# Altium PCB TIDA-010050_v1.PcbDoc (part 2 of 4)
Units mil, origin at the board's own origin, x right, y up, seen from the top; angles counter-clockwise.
Board outline 2060.77 x 1300 mil, 4 copper layers (Top Layer, signal1, signal2, Bottom Layer), stack 23.6 mil thick; 58 components, 30 nets, 158 pads, 41 vias.
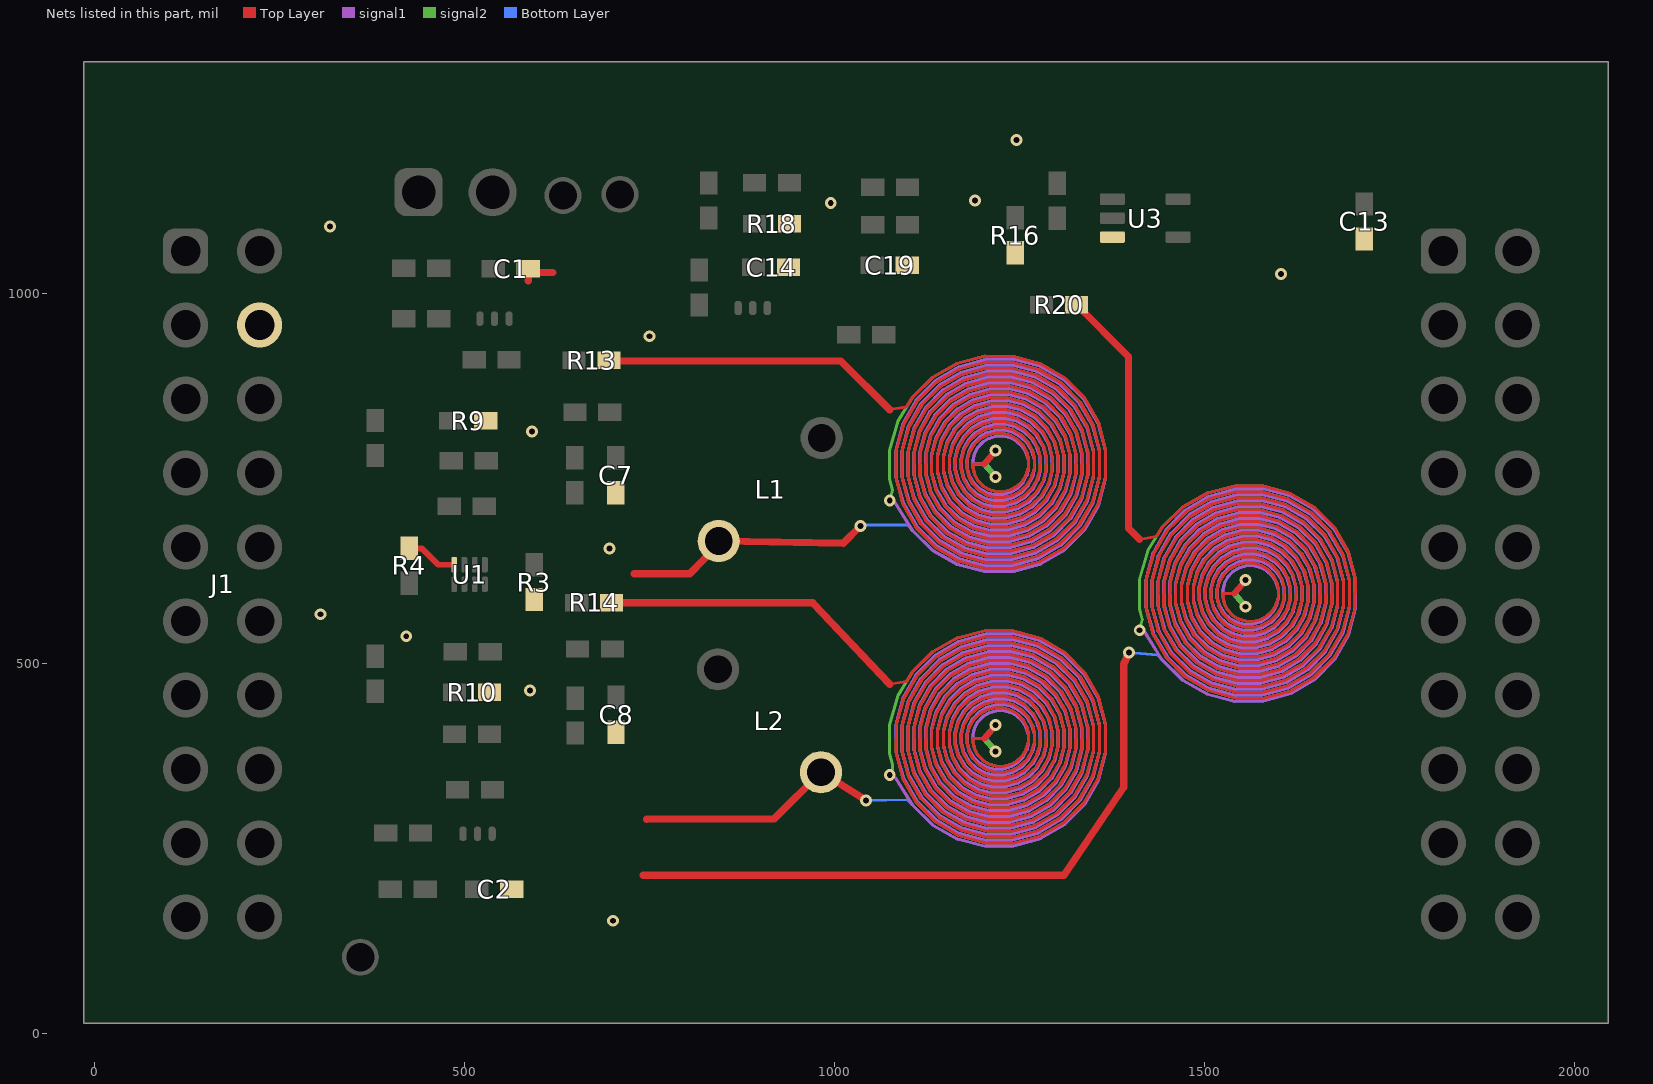
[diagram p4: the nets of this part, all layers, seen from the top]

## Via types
v1: diameter 16, hole 8, Top Layer to Bottom Layer, 40 vias
v2: diameter 16/16/16/16 (per signal layer), hole 8, Top Layer to Bottom Layer, 1 vias

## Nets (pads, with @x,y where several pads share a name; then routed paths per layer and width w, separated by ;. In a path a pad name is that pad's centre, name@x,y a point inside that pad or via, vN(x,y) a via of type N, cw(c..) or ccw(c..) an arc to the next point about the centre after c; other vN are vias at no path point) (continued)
GND: C1.2 C2.2 C7.2 C8.2 C13.2 C14.2 C19.2 J1.4 L1.1 L2.1 R3.1 R4.1 R9.1 R10.1 R13.1 R14.1 R16.1 R18.1 R20.1 U1.4 U3.3 | length 100215
  Top Layer w4: 1074.32,471.5 1096.71,475.12 1105.24,488.24 1132.74,515.27 1166.23,534.22 1203.4,543.83 1241.69,543.5 1278.52,533.29 1311.37,513.94 1338.03,486.8 1356.71,453.77 1366.19,417.12 1365.86,379.34 1355.78,343.03 1336.69,310.64 1309.93,284.35 1277.36,265.93 1241.21,256.59 1203.97,256.92 1168.16,266.86 1136.22,285.68 1110.31,312.07 1092.15,344.19 1082.94,379.83 1083.28,416.55 1093.08,451.84 1111.64,483.32 1137.66,508.87 1169.32,526.76 1204.45,535.83 1240.64,535.5 1275.43,525.83 1306.46,507.53 1331.63,481.89 1349.26,450.69 1358.19,416.06 1357.86,380.4 1348.33,346.12 1330.29,315.55 1305.02,290.75 1274.27,273.38 1240.16,264.59 1205.02,264.92 1171.25,274.31 1141.13,292.08 1116.71,316.98 1099.6,347.28 1090.94,380.88 1091.28,415.49 1100.54,448.76 1118.04,478.41 1142.57,502.47 1172.41,519.31 1205.5,527.83 1239.59,527.5 1272.34,518.38 1301.54,501.13 1325.22,476.98 1341.8,447.6 1350.19,415.01 1349.86,381.45 1340.87,349.2 1323.89,320.46 1300.11,297.15 1271.18,280.84 1239.11,272.59 1206.07,272.92 1174.34,281.77 1146.05,298.49 1123.11,321.89 1107.06,350.36 1098.94,381.93 1099.28,414.44 1107.99,445.67 1124.44,473.5 1147.48,496.06 1175.49,511.85 1206.56,519.83 1238.54,519.5 1269.25,510.92 1296.63,494.73 1318.82,472.07 1334.35,444.51 1342.19,413.96 1341.86,382.5 1333.42,352.29 1317.49,325.37 1295.2,303.55 1268.1,288.29 1238.05,280.59 1207.13,280.92 1177.42,289.22 1150.96,304.89 1129.51,326.8 1114.51,353.45 1106.94,382.99 1107.28,413.39 1115.44,442.58 1130.85,468.59 1152.39,489.66 1178.58,504.4 1207.61,511.83 1237.48,511.5 1266.17,503.47 1291.72,488.33 1312.42,467.16 1326.89,441.42 1334.19,412.9 1333.86,383.56 1325.96,355.38 1311.09,330.28 1290.29,309.95 1265.01,295.75 1237,288.59 1208.18,288.92 1180.51,296.68 1155.87,311.29 1135.91,331.72 1121.97,356.54 1114.94,384.04 1115.28,412.33 1122.9,439.49 1137.25,463.68 1157.3,483.26 1181.67,496.94 1208.66,503.83 1236.43,503.5 1263.08,496.01 1286.81,481.93 1306.02,462.24 1319.44,438.33 1326.19,411.85 1325.86,384.61 1318.51,358.47 1304.69,335.2 1285.37,316.36 1261.92,303.2 1235.95,296.59 1209.23,296.92 1183.6,304.13 1160.78,317.69 1142.32,336.63 1129.42,359.63 1122.94,385.09 1123.28,411.28 1130.35,436.4 1143.65,458.76 1162.22,476.86 1184.76,489.49 1209.71,495.83 1235.38,495.5 1259.99,488.56 1281.89,475.53 1299.62,457.33 1311.98,435.25 1318.19,410.8 1317.86,385.66 1311.05,361.56 1298.28,340.11 1280.46,322.76 1258.83,310.65 1234.89,304.59 1210.29,304.92 1186.69,311.59 1165.7,324.09 1148.72,341.54 1136.88,362.71 1130.94,386.15 1131.28,410.23 1137.81,433.32 1150.05,453.85 1167.13,470.46 1187.85,482.03 1210.77,487.83 1234.32,487.5 1256.9,481.1 1276.98,469.12 1293.22,452.42 1304.53,432.16 1310.19,409.74 1309.86,386.72 1303.6,364.64 1291.88,345.02 1275.55,329.16 1255.74,318.11 1233.84,312.59 1211.34,312.92 1189.78,319.04 1170.61,330.49 1155.12,346.45 1144.33,365.8 1138.94,387.2 1139.28,409.17 1145.26,430.23 1156.45,448.94 1172.04,464.06 1190.93,474.58 1211.82,479.83 1233.27,479.5 1253.81,473.65 1272.07,462.72 1286.81,447.51 1297.07,429.07 1302.19,408.69 1301.86,387.77 1296.14,367.73 1285.48,349.93 1270.64,335.56 1252.66,325.56 1232.79,320.59 1212.39,320.92 1192.86,326.5 1175.52,336.89 1161.52,351.37 1151.79,368.89 1146.94,388.25 1147.28,408.12 1152.72,427.14 1162.85,444.03 1176.95,457.65 1194.02,467.12 1212.87,471.83 1232.22,471.5 1250.73,466.19 1267.16,456.32 1280.41,442.59 1289.62,425.98 1294.19,407.64 1293.86,388.82 1288.69,370.82 1279.08,354.84 1265.73,341.96 1249.57,333.02 1231.73,328.59 1213.44,328.92 1195.95,333.95 1180.43,343.3 1167.92,356.28 1159.24,371.98 1154.94,389.31 1155.28,407.07 1160.17,424.05 1169.26,439.12 1181.86,451.25 1197.11,459.67 1213.93,463.83 1231.16,463.5 1247.64,458.74 1262.25,449.92 1274.01,437.68 1282.16,422.89 1286.19,406.58 1285.86,389.88 1281.23,373.91 1272.68,359.76 1260.81,348.36 1246.48,340.47 1230.68,336.59 1214.5,336.92 1199.04,341.41 1185.34,349.7 1174.32,361.19 1166.7,375.07 1162.94,390.36 1163.28,406.01 1167.63,420.96 1175.66,434.2 1186.78,444.85 1200.2,452.21 1214.98,455.83 1230.11,455.5 1244.55,451.28 1257.33,443.52 1267.61,432.77 1274.71,419.81 1278.19,405.53 1277.86,390.93 1273.78,377 1266.28,364.67 1255.9,354.77 1243.39,347.93 1229.63,344.59 1215.55,344.92 1202.13,348.86 1190.26,356.1 1180.72,366.1 1174.15,378.15 1170.94,391.41 1171.28,404.96 1175.08,417.88 1182.06,429.29 1191.69,438.45 1203.28,444.76 1216.03,447.83 1229.06,447.5 1241.46,443.83 1252.42,437.12 1261.21,427.86 1267.25,416.72 1270.19,404.48 1269.86,391.98 1266.32,380.08 1259.87,369.58 1250.99,361.17 1240.31,355.38 1228.57,352.59 1216.6,352.92 1205.21,356.32 1195.17,362.5 1187.13,371.01 1181.61,381.24 1178.94,392.47 1179.28,403.91 1182.54,414.79 1188.46,424.38 1196.6,432.05 1206.37,437.3 1217.09,439.83 1228,439.5 1238.38,436.37 1247.51,430.71 1254.81,422.95 1259.8,413.63 1262.19,403.42 1261.86,393.04 1258.87,383.17 1253.47,374.49 1246.08,367.57 1237.22,362.84 1227.52,360.59 1217.66,360.92 1208.3,363.77 1200.08,368.9 1193.53,375.93 1189.06,384.33 1186.94,393.52 1187.28,398.21 1202.53,398.21 ; 1074.31,842.61 1096.71,846.24 1105.24,859.35 1132.74,886.38 1166.23,905.33 1203.39,914.94 1241.69,914.61 1278.51,904.4 1311.36,885.05 1338.02,857.92 1356.71,824.89 1366.19,788.23 1365.85,750.46 1355.78,714.14 1336.69,681.75 1309.93,655.46 1277.36,637.04 1241.21,627.7 1203.96,628.03 1168.16,637.97 1136.22,656.79 1110.3,683.18 1092.15,715.3 1082.94,750.94 1083.27,787.66 1093.08,822.96 1111.64,854.44 1137.65,879.98 1169.31,897.88 1204.45,906.94 1240.64,906.61 1275.43,896.94 1306.45,878.65 1331.62,853 1349.25,821.8 1358.19,787.18 1357.85,751.51 1348.32,717.23 1330.29,686.66 1305.02,661.86 1274.27,644.49 1240.16,635.7 1205.02,636.03 1171.24,645.43 1141.13,663.2 1116.71,688.09 1099.6,718.39 1090.94,751.99 1091.27,786.61 1100.53,819.87 1118.04,849.52 1142.56,873.58 1172.4,890.42 1205.5,898.94 1239.58,898.61 1272.34,889.49 1301.54,872.24 1325.22,848.09 1341.8,818.71 1350.19,786.12 1349.85,752.56 1340.87,720.32 1323.89,691.57 1300.11,668.26 1271.18,651.95 1239.1,643.7 1206.07,644.03 1174.33,652.88 1146.04,669.6 1123.11,693.01 1107.05,721.48 1098.94,753.05 1099.27,785.55 1107.99,816.78 1124.44,844.61 1147.48,867.18 1175.49,882.97 1206.55,890.94 1238.53,890.61 1269.25,882.03 1296.63,865.84 1318.82,843.18 1334.34,815.62 1342.19,785.07 1341.85,753.62 1333.41,723.41 1317.49,696.48 1295.19,674.67 1268.09,659.4 1238.05,651.7 1207.12,652.03 1177.42,660.33 1150.96,676 1129.51,697.92 1114.51,724.56 1106.94,754.1 1107.27,784.5 1115.44,813.69 1130.84,839.7 1152.39,860.77 1178.58,875.51 1207.6,882.94 1237.48,882.61 1266.16,874.58 1291.72,859.44 1312.42,838.27 1326.89,812.53 1334.19,784.02 1333.85,754.67 1325.96,726.49 1311.08,701.4 1290.28,681.07 1265.01,666.86 1237,659.7 1208.18,660.03 1180.51,667.79 1155.87,682.4 1135.91,702.83 1121.96,727.65 1114.94,755.15 1115.27,783.45 1122.9,810.6 1137.24,834.79 1157.3,854.37 1181.67,868.06 1208.66,874.94 1236.43,874.61 1263.08,867.12 1286.8,853.04 1306.02,833.36 1319.44,809.45 1326.19,782.96 1325.85,755.72 1318.5,729.58 1304.68,706.31 1285.37,687.47 1261.92,674.31 1235.94,667.7 1209.23,668.03 1183.6,675.24 1160.78,688.8 1142.31,707.74 1129.42,730.74 1122.94,756.2 1123.27,782.39 1130.35,807.52 1143.65,829.88 1162.21,847.97 1184.75,860.6 1209.71,866.94 1235.37,866.61 1259.99,859.67 1281.89,846.64 1299.61,828.44 1311.98,806.36 1318.19,781.91 1317.85,756.78 1311.05,732.67 1298.28,711.22 1280.46,693.87 1258.83,681.77 1234.89,675.7 1210.28,676.03 1186.68,682.7 1165.69,695.2 1148.71,712.65 1136.87,733.83 1130.94,757.26 1131.27,781.34 1137.81,804.43 1150.05,824.96 1167.12,841.57 1187.84,853.15 1210.76,858.94 1234.32,858.61 1256.9,852.21 1276.98,840.24 1293.21,823.53 1304.53,803.27 1310.19,780.86 1309.85,757.83 1303.59,735.76 1291.88,716.13 1275.55,700.27 1255.74,689.22 1233.84,683.7 1211.34,684.03 1189.77,690.15 1170.6,701.61 1155.12,717.57 1144.33,736.91 1138.94,758.31 1139.27,780.29 1145.26,801.34 1156.45,820.05 1172.04,835.17 1190.93,845.69 1211.82,850.94 1233.27,850.61 1253.81,844.76 1272.07,833.83 1286.81,818.62 1297.07,800.18 1302.19,779.8 1301.85,758.88 1296.14,738.84 1285.48,721.05 1270.63,706.67 1252.65,696.68 1232.78,691.7 1212.39,692.03 1192.86,697.61 1175.52,708.01 1161.52,722.48 1151.78,740 1146.94,759.36 1147.27,779.23 1152.72,798.25 1162.85,815.14 1176.95,828.77 1194.02,838.24 1212.87,842.94 1232.21,842.61 1250.72,837.3 1267.15,827.43 1280.41,813.71 1289.62,797.09 1294.19,778.75 1293.85,759.94 1288.68,741.93 1279.08,725.96 1265.72,713.08 1249.57,704.13 1231.73,699.7 1213.44,700.03 1195.95,705.06 1180.43,714.41 1167.92,727.39 1159.24,743.09 1154.94,760.42 1155.27,778.18 1160.17,795.16 1169.25,810.23 1181.86,822.37 1197.11,830.78 1213.92,834.94 1231.16,834.61 1247.64,829.85 1262.24,821.03 1274.01,808.8 1282.16,794.01 1286.19,777.7 1285.85,760.99 1281.23,745.02 1272.67,730.87 1260.81,719.48 1246.48,711.59 1230.68,707.7 1214.49,708.03 1199.04,712.52 1185.34,720.81 1174.32,732.3 1166.69,746.18 1162.94,761.47 1163.27,777.13 1167.63,792.08 1175.65,805.32 1186.77,815.96 1200.19,823.33 1214.98,826.94 1230.11,826.61 1244.55,822.4 1257.33,814.63 1267.61,803.88 1274.71,790.92 1278.19,776.64 1277.85,762.04 1273.77,748.11 1266.27,735.78 1255.9,725.88 1243.39,719.04 1229.62,715.7 1215.55,716.03 1202.12,719.97 1190.25,727.21 1180.72,737.21 1174.15,749.27 1170.94,762.52 1171.27,776.07 1175.08,788.99 1182.06,800.4 1191.69,809.56 1203.28,815.87 1216.03,818.94 1229.05,818.61 1241.46,814.94 1252.42,808.23 1261.2,798.97 1267.25,787.83 1270.19,775.59 1269.85,763.09 1266.32,751.2 1259.87,740.69 1250.99,732.28 1240.3,726.5 1228.57,723.7 1216.6,724.03 1205.21,727.43 1195.16,733.61 1187.12,742.13 1181.6,752.35 1178.94,763.58 1179.27,775.02 1182.53,785.9 1188.46,795.49 1196.6,803.16 1206.37,808.42 1217.08,810.94 1228,810.61 1238.37,807.49 1247.51,801.83 1254.8,794.06 1259.8,784.74 1262.19,774.54 1261.85,764.15 1258.86,754.28 1253.47,745.61 1246.07,738.68 1237.21,733.95 1227.52,731.7 1217.65,732.03 1208.3,734.88 1200.08,740.02 1193.52,747.04 1189.06,755.44 1186.94,764.63 1187.27,769.32 1202.52,769.32 ; 1412.11,667.35 1434.5,670.98 1443.03,684.09 1470.53,711.12 1504.02,730.07 1541.19,739.68 1579.49,739.35 1616.31,729.14 1649.16,709.79 1675.82,682.66 1694.5,649.63 1703.98,612.97 1703.65,575.2 1693.57,538.88 1674.48,506.49 1647.73,480.2 1615.15,461.78 1579,452.44 1541.76,452.77 1505.95,462.71 1474.01,481.54 1448.1,507.92 1429.94,540.04 1420.74,575.68 1421.07,612.4 1430.87,647.7 1449.43,679.18 1475.45,704.72 1507.11,722.62 1542.24,731.68 1578.43,731.35 1613.22,721.68 1644.25,703.39 1669.42,677.75 1687.05,646.54 1695.98,611.92 1695.65,576.25 1686.12,541.97 1668.08,511.4 1642.81,486.6 1612.06,469.23 1577.95,460.44 1542.81,460.77 1509.04,470.17 1478.93,487.94 1454.5,512.83 1437.39,543.13 1428.74,576.73 1429.07,611.35 1438.33,644.61 1455.83,674.27 1480.36,698.32 1510.2,715.16 1543.29,723.68 1577.38,723.35 1610.13,714.23 1639.33,696.99 1663.02,672.83 1679.59,643.45 1687.98,610.86 1687.65,577.3 1678.66,545.06 1661.68,516.31 1637.9,493.01 1608.98,476.69 1576.9,468.44 1543.86,468.77 1512.13,477.62 1483.84,494.34 1460.9,517.75 1444.85,546.22 1436.74,577.79 1437.07,610.29 1445.78,641.52 1462.24,669.35 1485.27,691.92 1513.28,707.71 1544.35,715.68 1576.33,715.35 1607.05,706.77 1634.42,690.58 1656.61,667.92 1672.14,640.36 1679.98,609.81 1679.65,578.36 1671.21,548.15 1655.28,521.23 1632.99,499.41 1605.89,484.14 1575.84,476.44 1544.92,476.77 1515.21,485.08 1488.75,500.74 1467.3,522.66 1452.3,549.3 1444.74,578.84 1445.07,609.24 1453.24,638.43 1468.64,664.44 1490.18,685.52 1516.37,700.25 1545.4,707.68 1575.27,707.35 1603.96,699.32 1629.51,684.18 1650.21,663.01 1664.68,637.28 1671.98,608.76 1671.65,579.41 1663.75,551.23 1648.88,526.14 1628.08,505.81 1602.8,491.6 1574.79,484.44 1545.97,484.77 1518.3,492.53 1493.66,507.14 1473.71,527.57 1459.76,552.39 1452.74,579.89 1453.07,608.19 1460.69,635.35 1475.04,659.53 1495.09,679.11 1519.46,692.8 1546.45,699.68 1574.22,699.35 1600.87,691.87 1624.6,677.78 1643.81,658.1 1657.23,634.19 1663.98,607.7 1663.65,580.46 1656.3,554.32 1642.48,531.05 1623.17,512.21 1599.71,499.05 1573.74,492.44 1547.02,492.77 1521.39,499.99 1498.57,513.54 1480.11,532.48 1467.21,555.48 1460.74,580.95 1461.07,607.13 1468.15,632.26 1481.44,654.62 1500.01,672.71 1522.55,685.34 1547.51,691.68 1573.17,691.35 1597.78,684.41 1619.69,671.38 1637.41,653.18 1649.78,631.1 1655.98,606.65 1655.65,581.52 1648.84,557.41 1636.08,535.96 1618.25,518.61 1596.62,506.51 1572.68,500.44 1548.08,500.77 1524.48,507.44 1503.49,519.95 1486.51,537.39 1474.67,558.57 1468.74,582 1469.07,606.08 1475.6,629.17 1487.84,649.71 1504.92,666.31 1525.64,677.89 1548.56,683.68 1572.11,683.35 1594.69,676.96 1614.77,664.98 1631.01,648.27 1642.32,628.01 1647.98,605.6 1647.65,582.57 1641.39,560.5 1629.67,540.87 1613.34,525.01 1593.54,513.96 1571.63,508.44 1549.13,508.77 1527.57,514.9 1508.4,526.35 1492.91,542.31 1482.12,561.66 1476.74,583.05 1477.07,605.03 1483.06,626.08 1494.24,644.79 1509.83,659.91 1528.72,670.43 1549.61,675.68 1571.06,675.35 1591.61,669.5 1609.86,658.58 1624.61,643.36 1634.87,624.92 1639.98,604.54 1639.65,583.62 1633.93,563.59 1623.27,545.79 1608.43,531.41 1590.45,521.42 1570.58,516.44 1550.18,516.77 1530.65,522.35 1513.31,532.75 1499.31,547.22 1489.58,564.74 1484.74,584.11 1485.07,603.97 1490.51,622.99 1500.65,639.88 1514.74,653.51 1531.81,662.98 1550.67,667.68 1570.01,667.35 1588.52,662.05 1604.95,652.17 1618.2,638.45 1627.41,621.84 1631.98,603.49 1631.65,584.68 1626.48,566.67 1616.87,550.7 1603.52,537.82 1587.36,528.87 1569.52,524.44 1551.24,524.77 1533.74,529.8 1518.22,539.15 1505.71,552.13 1497.03,567.83 1492.74,585.16 1493.07,602.92 1497.97,619.91 1507.05,634.97 1519.66,647.11 1534.9,655.52 1551.72,659.68 1568.95,659.35 1585.43,654.59 1600.04,645.77 1611.8,633.54 1619.96,618.75 1623.98,602.44 1623.65,585.73 1619.02,569.76 1610.47,555.61 1598.6,544.22 1584.27,536.33 1568.47,532.44 1552.29,532.77 1536.83,537.26 1523.14,545.55 1512.11,557.04 1504.49,570.92 1500.74,586.21 1501.07,601.87 1505.42,616.82 1513.45,630.06 1524.57,640.7 1537.99,648.07 1552.77,651.68 1567.9,651.35 1582.34,647.14 1595.13,639.37 1605.4,628.62 1612.5,615.66 1615.98,601.38 1615.65,586.78 1611.57,572.85 1604.07,560.52 1593.69,550.62 1581.18,543.78 1567.42,540.44 1553.34,540.77 1539.92,544.71 1528.05,551.95 1518.52,561.96 1511.94,574.01 1508.74,587.27 1509.07,600.81 1512.87,613.73 1519.85,625.14 1529.48,634.3 1541.08,640.61 1553.83,643.68 1566.85,643.35 1579.25,639.68 1590.21,632.97 1599,623.71 1605.05,612.57 1607.98,600.33 1607.65,587.84 1604.11,575.94 1597.67,565.43 1588.78,557.02 1578.1,551.24 1566.36,548.44 1554.4,548.77 1543.01,552.17 1532.96,558.35 1524.92,566.87 1519.4,577.1 1516.74,588.32 1517.07,599.76 1520.33,610.64 1526.25,620.23 1534.39,627.9 1544.16,633.16 1554.88,635.68 1565.79,635.35 1576.17,632.23 1585.3,626.57 1592.6,618.8 1597.59,609.48 1599.98,599.28 1599.65,588.89 1596.66,579.03 1591.26,570.35 1583.87,563.42 1575.01,558.69 1565.31,556.44 1555.45,556.77 1546.09,559.62 1537.87,564.76 1531.32,571.78 1526.85,580.18 1524.74,589.37 1525.07,594.06 1540.32,594.06
  Top Layer w8: R4.1@425.05,655.21 441.91,655.21 464.15,632.97 U1.4@485.93,632.97 ; R14.1@698.53,577.28 R14.1@698.54,581.54 ; 1202.52,769.32 v1@1217.75,787.29 ; 1202.53,398.21 v1@1217.76,416.18 ; 1540.32,594.06 v1@1555.55,612.03
  Top Layer w10: 585.97,1016.51 C1.2@585.97,1033.33 591.3,1028 619,1028 ; R13.1@693.89,908.4 1008.53,908.4 1074.31,842.61 ; R14.1@698.54,581.54 970.36,581.54 972,579.9 1074.32,471.5 ; 728.9,620.94 804.04,620.94 L1.1@843.33,661.1 ; 741,213.42 1309.87,213.42 1390.63,332 1390.63,497.9 v1(1397.9,514.36) ; 746,289.14 918.48,289.48 L2.1@981.52,352.53 L2.1@1004.52,352.53 ; L1.1@843.33,665.1 1011.48,662 v1(1034.95,685.47) ; L2.1@981.52,354.53 982.08,352.7 v1(1042.51,314.54) ; L2.1@981.52,362.53 L2.1@986.64,362.53 ; R20.1@1326.94,984.74 1397.28,914.4 1397.28,682.18 1412.11,667.35
  signal1 w4: v1(1074.54,348.68) 1081.7,345.41 1105.24,308.18 1132.74,281.15 1166.23,262.2 1203.4,252.59 1241.69,252.92 1278.52,263.13 1311.37,282.48 1338.03,309.61 1356.71,342.64 1366.19,379.3 1365.86,417.07 1355.78,453.39 1336.69,485.78 1309.93,512.07 1277.36,530.49 1241.21,539.83 1203.97,539.5 1168.16,529.56 1136.22,510.73 1110.31,484.35 1092.15,452.23 1082.94,416.59 1083.28,379.87 1093.08,344.57 1111.64,313.09 1137.66,287.55 1169.32,269.65 1204.45,260.59 1240.64,260.92 1275.43,270.59 1306.46,288.88 1331.63,314.52 1349.26,345.73 1358.19,380.35 1357.86,416.02 1348.33,450.3 1330.29,480.87 1305.02,505.67 1274.27,523.04 1240.16,531.83 1205.02,531.5 1171.25,522.1 1141.13,504.33 1116.71,479.44 1099.6,449.14 1090.94,415.54 1091.28,380.92 1100.54,347.66 1118.04,318 1142.57,293.95 1172.41,277.11 1205.5,268.59 1239.59,268.92 1272.34,278.04 1301.54,295.28 1325.22,319.44 1341.8,348.82 1350.19,381.41 1349.86,414.97 1340.87,447.21 1323.89,475.96 1300.11,499.26 1271.18,515.58 1239.11,523.83 1206.07,523.5 1174.34,514.65 1146.05,497.93 1123.11,474.52 1107.06,446.05 1098.94,414.48 1099.28,381.98 1107.99,350.75 1124.44,322.92 1147.48,300.35 1175.49,284.56 1206.56,276.59 1238.54,276.92 1269.25,285.49 1296.63,301.69 1318.82,324.35 1334.35,351.91 1342.19,382.46 1341.86,413.91 1333.42,444.12 1317.49,471.04 1295.2,492.86 1268.1,508.13 1238.05,515.83 1207.13,515.5 1177.42,507.19 1150.96,491.53 1129.51,469.61 1114.51,442.97 1106.94,413.43 1107.28,383.03 1115.44,353.84 1130.85,327.83 1152.39,306.75 1178.58,292.02 1207.61,284.59 1237.48,284.92 1266.17,292.95 1291.72,308.09 1312.42,329.26 1326.89,354.99 1334.19,383.51 1333.86,412.86 1325.96,441.04 1311.09,466.13 1290.29,486.46 1265.01,500.67 1237,507.83 1208.18,507.5 1180.51,499.74 1155.87,485.13 1135.91,464.7 1121.97,439.88 1114.94,412.38 1115.28,384.08 1122.9,356.92 1137.25,332.74 1157.3,313.16 1181.67,299.47 1208.66,292.59 1236.43,292.92 1263.08,300.4 1286.81,314.49 1306.02,334.17 1319.44,358.08 1326.19,384.57 1325.86,411.81 1318.51,437.95 1304.69,461.22 1285.37,480.06 1261.92,493.22 1235.95,499.83 1209.23,499.5 1183.6,492.28 1160.78,478.73 1142.32,459.79 1129.42,436.79 1122.94,411.32 1123.28,385.14 1130.35,360.01 1143.65,337.65 1162.22,319.56 1184.76,306.93 1209.71,300.59 1235.38,300.92 1259.99,307.86 1281.89,320.89 1299.62,339.09 1311.98,361.17 1318.19,385.62 1317.86,410.75 1311.05,434.86 1298.28,456.31 1280.46,473.66 1258.83,485.76 1234.89,491.83 1210.29,491.5 1186.69,484.83 1165.7,472.32 1148.72,454.88 1136.88,433.7 1130.94,410.27 1131.28,386.19 1137.81,363.1 1150.05,342.56 1167.13,325.96 1187.85,314.38 1210.77,308.59 1234.32,308.92 1256.9,315.31 1276.98,327.29 1293.22,344 1304.53,364.26 1310.19,386.67 1309.86,409.7 1303.6,431.77 1291.88,451.4 1275.55,467.26 1255.74,478.31 1233.84,483.83 1211.34,483.5 1189.78,477.37 1170.61,465.92 1155.12,449.96 1144.33,430.61 1138.94,409.22 1139.28,387.24 1145.26,366.19 1156.45,347.48 1172.04,332.36 1190.93,321.84 1211.82,316.59 1233.27,316.92 1253.81,322.77 1272.07,333.69 1286.81,348.91 1297.07,367.35 1302.19,387.73 1301.86,408.65 1296.14,428.68 1285.48,446.48 1270.64,460.86 1252.66,470.85 1232.79,475.83 1212.39,475.5 1192.86,469.92 1175.52,459.52 1161.52,445.05 1151.79,427.53 1146.94,408.16 1147.28,388.3 1152.72,369.28 1162.85,352.39 1176.95,338.76 1194.02,329.29 1212.87,324.59 1232.22,324.92 1250.73,330.22 1267.16,340.1 1280.41,353.82 1289.62,370.43 1294.19,388.78 1293.86,407.59 1288.69,425.6 1279.08,441.57 1265.73,454.45 1249.57,463.4 1231.73,467.83 1213.44,467.5 1195.95,462.46 1180.43,453.12 1167.92,440.14 1159.24,424.44 1154.94,407.11 1155.28,389.35 1160.17,372.36 1169.26,357.3 1181.86,345.16 1197.11,336.75 1213.93,332.59 1231.16,332.92 1247.64,337.68 1262.25,346.5 1274.01,358.73 1282.16,373.52 1286.19,389.83 1285.86,406.54 1281.23,422.51 1272.68,436.66 1260.81,448.05 1246.48,455.94 1230.68,459.83 1214.5,459.5 1199.04,455.01 1185.34,446.72 1174.32,435.23 1166.7,421.35 1162.94,406.06 1163.28,390.4 1167.63,375.45 1175.66,362.21 1186.78,351.57 1200.2,344.2 1214.98,340.59 1230.11,340.92 1244.55,345.13 1257.33,352.9 1267.61,363.65 1274.71,376.61 1278.19,390.89 1277.86,405.49 1273.78,419.42 1266.28,431.75 1255.9,441.65 1243.39,448.49 1229.63,451.83 1215.55,451.5 1202.13,447.56 1190.26,440.32 1180.72,430.31 1174.15,418.26 1170.94,405 1171.28,391.46 1175.08,378.54 1182.06,367.12 1191.69,357.97 1203.28,351.66 1216.03,348.59 1229.06,348.92 1241.46,352.59 1252.42,359.3 1261.21,368.56 1267.25,379.7 1270.19,391.94 1269.86,404.43 1266.32,416.33 1259.87,426.84 1250.99,435.25 1240.31,441.03 1228.57,443.83 1216.6,443.5 1205.21,440.1 1195.17,433.92 1187.13,425.4 1181.61,415.17 1178.94,403.95 1179.28,392.51 1182.54,381.63 1188.46,372.04 1196.6,364.37 1206.37,359.11 1217.09,356.59 1228,356.92 1238.38,360.04 1247.51,365.7 1254.81,373.47 1259.8,382.79 1262.19,392.99 1261.86,403.38 1258.87,413.24 1253.47,421.92 1246.08,428.85 1237.22,433.58 1227.52,435.83 1217.66,435.5 1208.3,432.65 1200.08,427.51 1193.53,420.49 1189.06,412.09 1186.94,402.9 1187.28,398.21 1202.53,398.21 ; v1(1074.53,719.79) 1081.7,716.52 1105.24,679.29 1132.74,652.26 1166.23,633.31 1203.39,623.7 1241.69,624.03 1278.51,634.24 1311.36,653.59 1338.02,680.72 1356.71,713.76 1366.19,750.41 1365.85,788.18 1355.78,824.5 1336.69,856.89 1309.93,883.18 1277.36,901.6 1241.21,910.94 1203.96,910.61 1168.16,900.67 1136.22,881.85 1110.3,855.46 1092.15,823.34 1082.94,787.7 1083.27,750.98 1093.08,715.69 1111.64,684.2 1137.65,658.66 1169.31,640.77 1204.45,631.7 1240.64,632.03 1275.43,641.7 1306.45,660 1331.62,685.64 1349.25,716.84 1358.19,751.47 1357.85,787.13 1348.32,821.41 1330.29,851.98 1305.02,876.78 1274.27,894.15 1240.16,902.94 1205.02,902.61 1171.24,893.22 1141.13,875.45 1116.71,850.55 1099.6,820.25 1090.94,786.65 1091.27,752.04 1100.53,718.77 1118.04,689.12 1142.56,665.06 1172.4,648.22 1205.5,639.7 1239.58,640.03 1272.34,649.15 1301.54,666.4 1325.22,690.55 1341.8,719.93 1350.19,752.52 1349.85,786.08 1340.87,818.32 1323.89,847.07 1300.11,870.38 1271.18,886.69 1239.1,894.94 1206.07,894.61 1174.33,885.76 1146.04,869.04 1123.11,845.64 1107.05,817.17 1098.94,785.6 1099.27,753.09 1107.99,721.86 1124.44,694.03 1147.48,671.46 1175.49,655.68 1206.55,647.7 1238.53,648.03 1269.25,656.61 1296.63,672.8 1318.82,695.46 1334.34,723.02 1342.19,753.57 1341.85,785.03 1333.41,815.24 1317.49,842.16 1295.19,863.98 1268.09,879.24 1238.05,886.94 1207.12,886.61 1177.42,878.31 1150.96,862.64 1129.51,840.72 1114.51,814.08 1106.94,784.54 1107.27,754.14 1115.44,724.95 1130.84,698.94 1152.39,677.87 1178.58,663.13 1207.6,655.7 1237.48,656.03 1266.16,664.06 1291.72,679.2 1312.42,700.37 1326.89,726.11 1334.19,754.63 1333.85,783.97 1325.96,812.15 1311.08,837.24 1290.28,857.57 1265.01,871.78 1237,878.94 1208.18,878.61 1180.51,870.85 1155.87,856.24 1135.91,835.81 1121.96,810.99 1114.94,783.49 1115.27,755.2 1122.9,728.04 1137.24,703.85 1157.3,684.27 1181.67,670.59 1208.66,663.7 1236.43,664.03 1263.08,671.52 1286.8,685.6 1306.02,705.29 1319.44,729.2 1326.19,755.68 1325.85,782.92 1318.5,809.06 1304.68,832.33 1285.37,851.17 1261.92,864.33 1235.94,870.94 1209.23,870.61 1183.6,863.4 1160.78,849.84 1142.31,830.9 1129.42,807.9 1122.94,782.44 1123.27,756.25 1130.35,731.12 1143.65,708.76 1162.21,690.67 1184.75,678.04 1209.71,671.7 1235.37,672.03 1259.99,678.97 1281.89,692 1299.61,710.2 1311.98,732.28 1318.19,756.73 1317.85,781.87 1311.05,805.97 1298.28,827.42 1280.46,844.77 1258.83,856.87 1234.89,862.94 1210.28,862.61 1186.68,855.94 1165.69,843.44 1148.71,825.99 1136.87,804.81 1130.94,781.38 1131.27,757.3 1137.81,734.21 1150.05,713.68 1167.12,697.07 1187.84,685.49 1210.76,679.7 1234.32,680.03 1256.9,686.43 1276.98,698.4 1293.21,715.11 1304.53,735.37 1310.19,757.78 1309.85,780.81 1303.59,802.88 1291.88,822.51 1275.55,838.37 1255.74,849.42 1233.84,854.94 1211.34,854.61 1189.77,848.49 1170.6,837.04 1155.12,821.08 1144.33,801.73 1138.94,780.33 1139.27,758.36 1145.26,737.3 1156.45,718.59 1172.04,703.47 1190.93,692.95 1211.82,687.7 1233.27,688.03 1253.81,693.88 1272.07,704.81 1286.81,720.02 1297.07,738.46 1302.19,758.84 1301.85,779.76 1296.14,799.8 1285.48,817.6 1270.63,831.97 1252.65,841.96 1232.78,846.94 1212.39,846.61 1192.86,841.03 1175.52,830.63 1161.52,816.16 1151.78,798.64 1146.94,779.28 1147.27,759.41 1152.72,740.39 1162.85,723.5 1176.95,709.87 1194.02,700.4 1212.87,695.7 1232.21,696.03 1250.72,701.34 1267.15,711.21 1280.41,724.93 1289.62,741.55 1294.19,759.89 1293.85,778.71 1288.68,796.71 1279.08,812.68 1265.72,825.57 1249.57,834.51 1231.73,838.94 1213.44,838.61 1195.95,833.58 1180.43,824.23 1167.92,811.25 1159.24,795.55 1154.94,778.22 1155.27,760.46 1160.17,743.48 1169.25,728.41 1181.86,716.28 1197.11,707.86 1213.92,703.7 1231.16,704.03 1247.64,708.79 1262.24,717.61 1274.01,729.85 1282.16,744.63 1286.19,760.94 1285.85,777.65 1281.23,793.62 1272.67,807.77 1260.81,819.16 1246.48,827.05 1230.68,830.94 1214.49,830.61 1199.04,826.12 1185.34,817.83 1174.32,806.34 1166.69,792.46 1162.94,777.17 1163.27,761.51 1167.63,746.56 1175.65,733.33 1186.77,722.68 1200.19,715.31 1214.98,711.7 1230.11,712.03 1244.55,716.25 1257.33,724.01 1267.61,734.76 1274.71,747.72 1278.19,762 1277.85,776.6 1273.77,790.53 1266.27,802.86 1255.9,812.76 1243.39,819.6 1229.62,822.94 1215.55,822.61 1202.12,818.67 1190.25,811.43 1180.72,801.43 1174.15,789.37 1170.94,776.12 1171.27,762.57 1175.08,749.65 1182.06,738.24 1191.69,729.08 1203.28,722.77 1216.03,719.7 1229.05,720.03 1241.46,723.7 1252.42,730.41 1261.2,739.67 1267.25,750.81 1270.19,763.05 1269.85,775.55 1266.32,787.45 1259.87,797.95 1250.99,806.36 1240.3,812.14 1228.57,814.94 1216.6,814.61 1205.21,811.21 1195.16,805.03 1187.12,796.51 1181.6,786.29 1178.94,775.06 1179.27,763.62 1182.53,752.74 1188.46,743.15 1196.6,735.48 1206.37,730.22 1217.08,727.7 1228,728.03 1238.37,731.16 1247.51,736.81 1254.8,744.58 1259.8,753.9 1262.19,764.1 1261.85,774.49 1258.86,784.36 1253.47,793.04 1246.07,799.96 1237.21,804.69 1227.52,806.94 1217.65,806.61 1208.3,803.76 1200.08,798.63 1193.52,791.6 1189.06,783.2 1186.94,774.01 1187.27,769.32 1202.52,769.32 ; v1(1412.33,544.53) 1419.49,541.26 1443.03,504.03 1470.53,477 1504.02,458.05 1541.19,448.44 1579.49,448.77 1616.31,458.98 1649.16,478.33 1675.82,505.47 1694.5,538.5 1703.98,575.15 1703.65,612.93 1693.57,649.24 1674.48,681.63 1647.73,707.92 1615.15,726.34 1579,735.68 1541.76,735.35 1505.95,725.41 1474.01,706.59 1448.1,680.2 1429.94,648.08 1420.74,612.44 1421.07,575.72 1430.87,540.43 1449.43,508.95 1475.45,483.4 1507.11,465.51 1542.24,456.44 1578.43,456.77 1613.22,466.44 1644.25,484.74 1669.42,510.38 1687.05,541.58 1695.98,576.21 1695.65,611.87 1686.12,646.15 1668.08,676.72 1642.81,701.52 1612.06,718.89 1577.95,727.68 1542.81,727.35 1509.04,717.96 1478.93,700.19 1454.5,675.29 1437.39,644.99 1428.74,611.39 1429.07,576.78 1438.33,543.51 1455.83,513.86 1480.36,489.8 1510.2,472.96 1543.29,464.44 1577.38,464.77 1610.13,473.89 1639.33,491.14 1663.02,515.29 1679.59,544.67 1687.98,577.26 1687.65,610.82 1678.66,643.07 1661.68,671.81 1637.9,695.12 1608.98,711.43 1576.9,719.68 1543.86,719.35 1512.13,710.5 1483.84,693.78 1460.9,670.38 1444.85,641.91 1436.74,610.34 1437.07,577.83 1445.78,546.6 1462.24,518.77 1485.27,496.21 1513.28,480.42 1544.35,472.44 1576.33,472.77 1607.05,481.35 1634.42,497.54 1656.61,520.2 1672.14,547.76 1679.98,578.31 1679.65,609.77 1671.21,639.98 1655.28,666.9 1632.99,688.72 1605.89,703.98 1575.84,711.68 1544.92,711.35 1515.21,703.05 1488.75,687.38 1467.3,665.47 1452.3,638.82 1444.74,609.28 1445.07,578.88 1453.24,549.69 1468.64,523.68 1490.18,502.61 1516.37,487.87 1545.4,480.44 1575.27,480.77 1603.96,488.8 1629.51,503.94 1650.21,525.11 1664.68,550.85 1671.98,579.37 1671.65,608.71 1663.75,636.89 1648.88,661.99 1628.08,682.32 1602.8,696.52 1574.79,703.68 1545.97,703.35 1518.3,695.59 1493.66,680.98 1473.71,660.55 1459.76,635.73 1452.74,608.23 1453.07,579.94 1460.69,552.78 1475.04,528.59 1495.09,509.01 1519.46,495.33 1546.45,488.44 1574.22,488.77 1600.87,496.26 1624.6,510.34 1643.81,530.03 1657.23,553.94 1663.98,580.42 1663.65,607.66 1656.3,633.8 1642.48,657.07 1623.17,675.91 1599.71,689.07 1573.74,695.68 1547.02,695.35 1521.39,688.14 1498.57,674.58 1480.11,655.64 1467.21,632.64 1460.74,607.18 1461.07,580.99 1468.15,555.87 1481.44,533.51 1500.01,515.41 1522.55,502.78 1547.51,496.44 1573.17,496.77 1597.78,503.71 1619.69,516.74 1637.41,534.94 1649.78,557.02 1655.98,581.47 1655.65,606.61 1648.84,630.71 1636.08,652.16 1618.25,669.51 1596.62,681.61 1572.68,687.68 1548.08,687.35 1524.48,680.68 1503.49,668.18 1486.51,650.73 1474.67,629.56 1468.74,606.12 1469.07,582.04 1475.6,558.95 1487.84,538.42 1504.92,521.81 1525.64,510.24 1548.56,504.44 1572.11,504.77 1594.69,511.17 1614.77,523.15 1631.01,539.85 1642.32,560.11 1647.98,582.53 1647.65,605.55 1641.39,627.63 1629.67,647.25 1613.34,663.11 1593.54,674.16 1571.63,679.68 1549.13,679.35 1527.57,673.23 1508.4,661.78 1492.91,645.82 1482.12,626.47 1476.74,605.07 1477.07,583.1 1483.06,562.04 1494.24,543.33 1509.83,528.21 1528.72,517.69 1549.61,512.44 1571.06,512.77 1591.61,518.62 1609.86,529.55 1624.61,544.76 1634.87,563.2 1639.98,583.58 1639.65,604.5 1633.93,624.54 1623.27,642.34 1608.43,656.71 1590.45,666.71 1570.58,671.68 1550.18,671.35 1530.65,665.77 1513.31,655.38 1499.31,640.9 1489.58,623.38 1484.74,604.02 1485.07,584.15 1490.51,565.13 1500.65,548.24 1514.74,534.62 1531.81,525.15 1550.67,520.44 1570.01,520.77 1588.52,526.08 1604.95,535.95 1618.2,549.68 1627.41,566.29 1631.98,584.63 1631.65,603.45 1626.48,621.45 1616.87,637.43 1603.52,650.31 1587.36,659.25 1569.52,663.68 1551.24,663.35 1533.74,658.32 1518.22,648.97 1505.71,635.99 1497.03,620.29 1492.74,602.96 1493.07,585.2 1497.97,568.22 1507.05,553.15 1519.66,541.02 1534.9,532.6 1551.72,528.44 1568.95,528.77 1585.43,533.53 1600.04,542.35 1611.8,554.59 1619.96,569.38 1623.98,585.69 1623.65,602.39 1619.02,618.36 1610.47,632.51 1598.6,643.91 1584.27,651.8 1568.47,655.68 1552.29,655.35 1536.83,650.86 1523.14,642.57 1512.11,631.08 1504.49,617.2 1500.74,601.91 1501.07,586.26 1505.42,571.31 1513.45,558.07 1524.57,547.42 1537.99,540.06 1552.77,536.44 1567.9,536.77 1582.34,540.99 1595.13,548.75 1605.4,559.5 1612.5,572.46 1615.98,586.74 1615.65,601.34 1611.57,615.27 1604.07,627.6 1593.69,637.5 1581.18,644.34 1567.42,647.68 1553.34,647.35 1539.92,643.41 1528.05,636.17 1518.52,626.17 1511.94,614.12 1508.74,600.86 1509.07,587.31 1512.87,574.39 1519.85,562.98 1529.48,553.82 1541.08,547.51 1553.83,544.44 1566.85,544.77 1579.25,548.44 1590.21,555.15 1599,564.41 1605.05,575.55 1607.98,587.79 1607.65,600.29 1604.11,612.19 1597.67,622.69 1588.78,631.1 1578.1,636.89 1566.36,639.68 1554.4,639.35 1543.01,635.95 1532.96,629.77 1524.92,621.26 1519.4,611.03 1516.74,599.8 1517.07,588.36 1520.33,577.48 1526.25,567.89 1534.39,560.22 1544.16,554.97 1554.88,552.44 1565.79,552.77 1576.17,555.9 1585.3,561.56 1592.6,569.32 1597.59,578.64 1599.98,588.85 1599.65,599.23 1596.66,609.1 1591.26,617.78 1583.87,624.7 1575.01,629.43 1565.31,631.68 1555.45,631.35 1546.09,628.5 1537.87,623.37 1531.32,616.34 1526.85,607.94 1524.74,598.75 1525.07,594.06 1540.32,594.06
  signal1 w8: 1202.52,769.32 v1@1217.75,787.29 ; 1202.53,398.21 v1@1217.76,416.18 ; 1540.32,594.06 v1@1555.55,612.03
  signal2 w4: v1(1074.54,348.68) 1078.07,354.19 1078.07,363.14 1074.32,377.67 1074.32,379.69 1073.99,416.41 1085.63,456.31 1105.71,488.7 ; v1(1074.53,719.79) 1078.07,734.25 1074.32,748.78 1074.32,750.8 1073.98,787.52 1085.62,827.42 1105.71,859.82 ; 1105.24,488.24 1105.71,488.7 ; 1105.24,859.35 1105.71,859.82 ; 1202.52,769.32 1187.27,769.32 1186.94,764.63 1189.06,755.44 1193.52,747.04 1200.08,740.02 1208.3,734.88 1217.65,732.03 1227.52,731.7 1237.21,733.95 1246.07,738.68 1253.47,745.61 1258.86,754.28 1261.85,764.15 1262.19,774.54 1259.8,784.74 1254.8,794.06 1247.51,801.83 1238.37,807.49 1228,810.61 1217.08,810.94 1206.37,808.42 1196.6,803.16 1188.46,795.49 1182.53,785.9 1179.27,775.02 1178.94,763.58 1181.6,752.35 1187.12,742.13 1195.16,733.61 1205.21,727.43 1216.6,724.03 1228.57,723.7 1240.3,726.5 1250.99,732.28 1259.87,740.69 1266.32,751.2 1269.85,763.09 1270.19,775.59 1267.25,787.83 1261.2,798.97 1252.42,808.23 1241.46,814.94 1229.05,818.61 1216.03,818.94 1203.28,815.87 1191.69,809.56 1182.06,800.4 1175.08,788.99 1171.27,776.07 1170.94,762.52 1174.15,749.27 1180.72,737.21 1190.25,727.21 1202.12,719.97 1215.55,716.03 1229.62,715.7 1243.39,719.04 1255.9,725.88 1266.27,735.78 1273.77,748.11 1277.85,762.04 1278.19,776.64 1274.71,790.92 1267.61,803.88 1257.33,814.63 1244.55,822.4 1230.11,826.61 1214.98,826.94 1200.19,823.33 1186.77,815.96 1175.65,805.32 1167.63,792.08 1163.27,777.13 1162.94,761.47 1166.69,746.18 1174.32,732.3 1185.34,720.81 1199.04,712.52 1214.49,708.03 1230.68,707.7 1246.48,711.59 1260.81,719.48 1272.67,730.87 1281.23,745.02 1285.85,760.99 1286.19,777.7 1282.16,794.01 1274.01,808.8 1262.24,821.03 1247.64,829.85 1231.16,834.61 1213.92,834.94 1197.11,830.78 1181.86,822.37 1169.25,810.23 1160.17,795.16 1155.27,778.18 1154.94,760.42 1159.24,743.09 1167.92,727.39 1180.43,714.41 1195.95,705.06 1213.44,700.03 1231.73,699.7 1249.57,704.13 1265.72,713.08 1279.08,725.96 1288.68,741.93 1293.85,759.94 1294.19,778.75 1289.62,797.09 1280.41,813.71 1267.15,827.43 1250.72,837.3 1232.21,842.61 1212.87,842.94 1194.02,838.24 1176.95,828.77 1162.85,815.14 1152.72,798.25 1147.27,779.23 1146.94,759.36 1151.78,740 1161.52,722.48 1175.52,708.01 1192.86,697.61 1212.39,692.03 1232.78,691.7 1252.65,696.68 1270.63,706.67 1285.48,721.05 1296.14,738.84 1301.85,758.88 1302.19,779.8 1297.07,800.18 1286.81,818.62 1272.07,833.83 1253.81,844.76 1233.27,850.61 1211.82,850.94 1190.93,845.69 1172.04,835.17 1156.45,820.05 1145.26,801.34 1139.27,780.29 1138.94,758.31 1144.33,736.91 1155.12,717.57 1170.6,701.61 1189.77,690.15 1211.34,684.03 1233.84,683.7 1255.74,689.22 1275.55,700.27 1291.88,716.13 1303.59,735.76 1309.85,757.83 1310.19,780.86 1304.53,803.27 1293.21,823.53 1276.98,840.24 1256.9,852.21 1234.32,858.61 1210.76,858.94 1187.84,853.15 1167.12,841.57 1150.05,824.96 1137.81,804.43 1131.27,781.34 1130.94,757.26 1136.87,733.83 1148.71,712.65 1165.69,695.2 1186.68,682.7 1210.28,676.03 1234.89,675.7 1258.83,681.77 1280.46,693.87 1298.28,711.22 1311.05,732.67 1317.85,756.78 1318.19,781.91 1311.98,806.36 1299.61,828.44 1281.89,846.64 1259.99,859.67 1235.37,866.61 1209.71,866.94 1184.75,860.6 1162.21,847.97 1143.65,829.88 1130.35,807.52 1123.27,782.39 1122.94,756.2 1129.42,730.74 1142.31,707.74 1160.78,688.8 1183.6,675.24 1209.23,668.03 1235.94,667.7 1261.92,674.31 1285.37,687.47 1304.68,706.31 1318.5,729.58 1325.85,755.72 1326.19,782.96 1319.44,809.45 1306.02,833.36 1286.8,853.04 1263.08,867.12 1236.43,874.61 1208.66,874.94 1181.67,868.06 1157.3,854.37 1137.24,834.79 1122.9,810.6 1115.27,783.45 1114.94,755.15 1121.96,727.65 1135.91,702.83 1155.87,682.4 1180.51,667.79 1208.18,660.03 1237,659.7 1265.01,666.86 1290.28,681.07 1311.08,701.4 1325.96,726.49 1333.85,754.67 1334.19,784.02 1326.89,812.53 1312.42,838.27 1291.72,859.44 1266.16,874.58 1237.48,882.61 1207.6,882.94 1178.58,875.51 1152.39,860.77 1130.84,839.7 1115.44,813.69 1107.27,784.5 1106.94,754.1 1114.51,724.56 1129.51,697.92 1150.96,676 1177.42,660.33 1207.12,652.03 1238.05,651.7 1268.09,659.4 1295.19,674.67 1317.49,696.48 1333.41,723.41 1341.85,753.62 1342.19,785.07 1334.34,815.62 1318.82,843.18 1296.63,865.84 1269.25,882.03 1238.53,890.61 1206.55,890.94 1175.49,882.97 1147.48,867.18 1124.44,844.61 1107.99,816.78 1099.27,785.55 1098.94,753.05 1107.05,721.48 1123.11,693.01 1146.04,669.6 1174.33,652.88 1206.07,644.03 1239.1,643.7 1271.18,651.95 1300.11,668.26 1323.89,691.57 1340.87,720.32 1349.85,752.56 1350.19,786.12 1341.8,818.71 1325.22,848.09 1301.54,872.24 1272.34,889.49 1239.58,898.61 1205.5,898.94 1172.4,890.42 1142.56,873.58 1118.04,849.52 1100.53,819.87 1091.27,786.61 1090.94,751.99 1099.6,718.39 1116.71,688.09 1141.13,663.2 1171.24,645.43 1205.02,636.03 1240.16,635.7 1274.27,644.49 1305.02,661.86 1330.29,686.66 1348.32,717.23 1357.85,751.51 1358.19,787.18 1349.25,821.8 1331.62,853 1306.45,878.65 1275.43,896.94 1240.64,906.61 1204.45,906.94 1169.31,897.88 1137.65,879.98 1111.64,854.44 1093.08,822.96 1083.27,787.66 1082.94,750.94 1086.69,736.4 1087.48,733.35 1092.15,715.3 1110.3,683.18 1136.22,656.79 1168.16,637.97 1203.96,628.03 1241.21,627.7 1277.36,637.04 1309.93,655.46 1336.69,681.75 1355.78,714.14 1365.85,750.46 1366.19,788.23 1356.71,824.89 1338.02,857.92 1311.36,885.05 1278.51,904.4 1241.69,914.61 1203.39,914.94 1166.23,905.33 1132.74,886.38 1105.71,859.82 ; 1202.53,398.21 1187.28,398.21 1186.94,393.52 1189.06,384.33 1193.53,375.93 1200.08,368.9 1208.3,363.77 1217.66,360.92 1227.52,360.59 1237.22,362.84 1246.08,367.57 1253.47,374.49 1258.87,383.17 1261.86,393.04 1262.19,403.42 1259.8,413.63 1254.81,422.95 1247.51,430.71 1238.38,436.37 1228,439.5 1217.09,439.83 1206.37,437.3 1196.6,432.05 1188.46,424.38 1182.54,414.79 1179.28,403.91 1178.94,392.47 1181.61,381.24 1187.13,371.01 1195.17,362.5 1205.21,356.32 1216.6,352.92 1228.57,352.59 1240.31,355.38 1250.99,361.17 1259.87,369.58 1266.32,380.08 1269.86,391.98 1270.19,404.48 1267.25,416.72 1261.21,427.86 1252.42,437.12 1241.46,443.83 1229.06,447.5 1216.03,447.83 1203.28,444.76 1191.69,438.45 1182.06,429.29 1175.08,417.88 1171.28,404.96 1170.94,391.41 1174.15,378.15 1180.72,366.1 1190.26,356.1 1202.13,348.86 1215.55,344.92 1229.63,344.59 1243.39,347.93 1255.9,354.77 1266.28,364.67 1273.78,377 1277.86,390.93 1278.19,405.53 1274.71,419.81 1267.61,432.77 1257.33,443.52 1244.55,451.28 1230.11,455.5 1214.98,455.83 1200.2,452.21 1186.78,444.85 1175.66,434.2 1167.63,420.96 1163.28,406.01 1162.94,390.36 1166.7,375.07 1174.32,361.19 1185.34,349.7 1199.04,341.41 1214.5,336.92 1230.68,336.59 1246.48,340.47 1260.81,348.36 1272.68,359.76 1281.23,373.91 1285.86,389.88 1286.19,406.58 1282.16,422.89 1274.01,437.68 1262.25,449.92 1247.64,458.74 1231.16,463.5 1213.93,463.83 1197.11,459.67 1181.86,451.25 1169.26,439.12 1160.17,424.05 1155.28,407.07 1154.94,389.31 1159.24,371.98 1167.92,356.28 1180.43,343.3 1195.95,333.95 1213.44,328.92 1231.73,328.59 1249.57,333.02 1265.73,341.96 1279.08,354.84 1288.69,370.82 1293.86,388.82 1294.19,407.64 1289.62,425.98 1280.41,442.59 1267.16,456.32 1250.73,466.19 1232.22,471.5 1212.87,471.83 1194.02,467.12 1176.95,457.65 1162.85,444.03 1152.72,427.14 1147.28,408.12 1146.94,388.25 1151.79,368.89 1161.52,351.37 1175.52,336.89 1192.86,326.5 1212.39,320.92 1232.79,320.59 1252.66,325.56 1270.64,335.56 1285.48,349.93 1296.14,367.73 1301.86,387.77 1302.19,408.69 1297.07,429.07 1286.81,447.51 1272.07,462.72 1253.81,473.65 1233.27,479.5 1211.82,479.83 1190.93,474.58 1172.04,464.06 1156.45,448.94 1145.26,430.23 1139.28,409.17 1138.94,387.2 1144.33,365.8 1155.12,346.45 1170.61,330.49 1189.78,319.04 1211.34,312.92 1233.84,312.59 1255.74,318.11 1275.55,329.16 1291.88,345.02 1303.6,364.64 1309.86,386.72 1310.19,409.74 1304.53,432.16 1293.22,452.42 1276.98,469.12 1256.9,481.1 1234.32,487.5 1210.77,487.83 1187.85,482.03 1167.13,470.46 1150.05,453.85 1137.81,433.32 1131.28,410.23 1130.94,386.15 1136.88,362.71 1148.72,341.54 1165.7,324.09 1186.69,311.59 1210.29,304.92 1234.89,304.59 1258.83,310.65 1280.46,322.76 1298.28,340.11 1311.05,361.56 1317.86,385.66 1318.19,410.8 1311.98,435.25 1299.62,457.33 1281.89,475.53 1259.99,488.56 1235.38,495.5 1209.71,495.83 1184.76,489.49 1162.22,476.86 1143.65,458.76 1130.35,436.4 1123.28,411.28 1122.94,385.09 1129.42,359.63 1142.32,336.63 1160.78,317.69 1183.6,304.13 1209.23,296.92 1235.95,296.59 1261.92,303.2 1285.37,316.36 1304.69,335.2 1318.51,358.47 1325.86,384.61 1326.19,411.85 1319.44,438.33 1306.02,462.24 1286.81,481.93 1263.08,496.01 1236.43,503.5 1208.66,503.83 1181.67,496.94 1157.3,483.26 1137.25,463.68 1122.9,439.49 1115.28,412.33 1114.94,384.04 1121.97,356.54 1135.91,331.72 1155.87,311.29 1180.51,296.68 1208.18,288.92 1237,288.59 1265.01,295.75 1290.29,309.95 1311.09,330.28 1325.96,355.38 1333.86,383.56 1334.19,412.9 1326.89,441.42 1312.42,467.16 1291.72,488.33 1266.17,503.47 1237.48,511.5 1207.61,511.83 1178.58,504.4 1152.39,489.66 1130.85,468.59 1115.44,442.58 1107.28,413.39 1106.94,382.99 1114.51,353.45 1129.51,326.8 1150.96,304.89 1177.42,289.22 1207.13,280.92 1238.05,280.59 1268.1,288.29 1295.2,303.55 1317.49,325.37 1333.42,352.29 1341.86,382.5 1342.19,413.96 1334.35,444.51 1318.82,472.07 1296.63,494.73 1269.25,510.92 1238.54,519.5 1206.56,519.83 1175.49,511.85 1147.48,496.06 1124.44,473.5 1107.99,445.67 1099.28,414.44 1098.94,381.93 1107.06,350.36 1123.11,321.89 1146.05,298.49 1174.34,281.77 1206.07,272.92 1239.11,272.59 1271.18,280.84 1300.11,297.15 1323.89,320.46 1340.87,349.2 1349.86,381.45 1350.19,415.01 1341.8,447.6 1325.22,476.98 1301.54,501.13 1272.34,518.38 1239.59,527.5 1205.5,527.83 1172.41,519.31 1142.57,502.47 1118.04,478.41 1100.54,448.76 1091.28,415.49 1090.94,380.88 1099.6,347.28 1116.71,316.98 1141.13,292.08 1171.25,274.31 1205.02,264.92 1240.16,264.59 1274.27,273.38 1305.02,290.75 1330.29,315.55 1348.33,346.12 1357.86,380.4 1358.19,416.06 1349.26,450.69 1331.63,481.89 1306.46,507.53 1275.43,525.83 1240.64,535.5 1204.45,535.83 1169.32,526.76 1137.66,508.87 1111.64,483.32 1093.08,451.84 1083.28,416.55 1082.94,379.83 1086.7,365.29 1087.49,362.24 1092.15,344.19 1110.31,312.07 1136.22,285.68 1168.16,266.86 1203.97,256.92 1241.21,256.59 1277.36,265.93 1309.93,284.35 1336.69,310.64 1355.78,343.03 1365.86,379.34 1366.19,417.12 1356.71,453.77 1338.03,486.8 1311.37,513.94 1278.52,533.29 1241.69,543.5 1203.4,543.83 1166.23,534.22 1132.74,515.27 1105.71,488.7 ; v1(1412.33,544.53) 1415.87,558.99 1412.11,573.52 1412.11,575.54 1411.78,612.26 1423.42,652.16 1443.5,684.56 ; 1443.03,684.09 1443.5,684.56 ; 1540.32,594.06 1525.07,594.06 1524.74,589.37 1526.85,580.18 1531.32,571.78 1537.87,564.76 1546.09,559.62 1555.45,556.77 1565.31,556.44 1575.01,558.69 1583.87,563.42 1591.26,570.35 1596.66,579.03 1599.65,588.89 1599.98,599.28 1597.59,609.48 1592.6,618.8 1585.3,626.57 1576.17,632.23 1565.79,635.35 1554.88,635.68 1544.16,633.16 1534.39,627.9 1526.25,620.23 1520.33,610.64 1517.07,599.76 1516.74,588.32 1519.4,577.1 1524.92,566.87 1532.96,558.35 1543.01,552.17 1554.4,548.77 1566.36,548.44 1578.1,551.24 1588.78,557.02 1597.67,565.43 1604.11,575.94 1607.65,587.84 1607.98,600.33 1605.05,612.57 1599,623.71 1590.21,632.97 1579.25,639.68 1566.85,643.35 1553.83,643.68 1541.08,640.61 1529.48,634.3 1519.85,625.14 1512.87,613.73 1509.07,600.81 1508.74,587.27 1511.94,574.01 1518.52,561.96 1528.05,551.95 1539.92,544.71 1553.34,540.77 1567.42,540.44 1581.18,543.78 1593.69,550.62 1604.07,560.52 1611.57,572.85 1615.65,586.78 1615.98,601.38 1612.5,615.66 1605.4,628.62 1595.13,639.37 1582.34,647.14 1567.9,651.35 1552.77,651.68 1537.99,648.07 1524.57,640.7 1513.45,630.06 1505.42,616.82 1501.07,601.87 1500.74,586.21 1504.49,570.92 1512.11,557.04 1523.14,545.55 1536.83,537.26 1552.29,532.77 1568.47,532.44 1584.27,536.33 1598.6,544.22 1610.47,555.61 1619.02,569.76 1623.65,585.73 1623.98,602.44 1619.96,618.75 1611.8,633.54 1600.04,645.77 1585.43,654.59 1568.95,659.35 1551.72,659.68 1534.9,655.52 1519.66,647.11 1507.05,634.97 1497.97,619.91 1493.07,602.92 1492.74,585.16 1497.03,567.83 1505.71,552.13 1518.22,539.15 1533.74,529.8 1551.24,524.77 1569.52,524.44 1587.36,528.87 1603.52,537.82 1616.87,550.7 1626.48,566.67 1631.65,584.68 1631.98,603.49 1627.41,621.84 1618.2,638.45 1604.95,652.17 1588.52,662.05 1570.01,667.35 1550.67,667.68 1531.81,662.98 1514.74,653.51 1500.65,639.88 1490.51,622.99 1485.07,603.97 1484.74,584.11 1489.58,564.74 1499.31,547.22 1513.31,532.75 1530.65,522.35 1550.18,516.77 1570.58,516.44 1590.45,521.42 1608.43,531.41 1623.27,545.79 1633.93,563.59 1639.65,583.62 1639.98,604.54 1634.87,624.92 1624.61,643.36 1609.86,658.58 1591.61,669.5 1571.06,675.35 1549.61,675.68 1528.72,670.43 1509.83,659.91 1494.24,644.79 1483.06,626.08 1477.07,605.03 1476.74,583.05 1482.12,561.66 1492.91,542.31 1508.4,526.35 1527.57,514.9 1549.13,508.77 1571.63,508.44 1593.54,513.96 1613.34,525.01 1629.67,540.87 1641.39,560.5 1647.65,582.57 1647.98,605.6 1642.32,628.01 1631.01,648.27 1614.77,664.98 1594.69,676.96 1572.11,683.35 1548.56,683.68 1525.64,677.89 1504.92,666.31 1487.84,649.71 1475.6,629.17 1469.07,606.08 1468.74,582 1474.67,558.57 1486.51,537.39 1503.49,519.95 1524.48,507.44 1548.08,500.77 1572.68,500.44 1596.62,506.51 1618.25,518.61 1636.08,535.96 1648.84,557.41 1655.65,581.52 1655.98,606.65 1649.78,631.1 1637.41,653.18 1619.69,671.38 1597.78,684.41 1573.17,691.35 1547.51,691.68 1522.55,685.34 1500.01,672.71 1481.44,654.62 1468.15,632.26 1461.07,607.13 1460.74,580.95 1467.21,555.48 1480.11,532.48 1498.57,513.54 1521.39,499.99 1547.02,492.77 1573.74,492.44 1599.71,499.05 1623.17,512.21 1642.48,531.05 1656.3,554.32 1663.65,580.46 1663.98,607.7 1657.23,634.19 1643.81,658.1 1624.6,677.78 1600.87,691.87 1574.22,699.35 1546.45,699.68 1519.46,692.8 1495.09,679.11 1475.04,659.53 1460.69,635.35 1453.07,608.19 1452.74,579.89 1459.76,552.39 1473.71,527.57 1493.66,507.14 1518.3,492.53 1545.97,484.77 1574.79,484.44 1602.8,491.6 1628.08,505.81 1648.88,526.14 1663.75,551.23 1671.65,579.41 1671.98,608.76 1664.68,637.28 1650.21,663.01 1629.51,684.18 1603.96,699.32 1575.27,707.35 1545.4,707.68 1516.37,700.25 1490.18,685.52 1468.64,664.44 1453.24,638.43 1445.07,609.24 1444.74,578.84 1452.3,549.3 1467.3,522.66 1488.75,500.74 1515.21,485.08 1544.92,476.77 1575.84,476.44 1605.89,484.14 1632.99,499.41 1655.28,521.23 1671.21,548.15 1679.65,578.36 1679.98,609.81 1672.14,640.36 1656.61,667.92 1634.42,690.58 1607.05,706.77 1576.33,715.35 1544.35,715.68 1513.28,707.71 1485.27,691.92 1462.24,669.35 1445.78,641.52 1437.07,610.29 1436.74,577.79 1444.85,546.22 1460.9,517.75 1483.84,494.34 1512.13,477.62 1543.86,468.77 1576.9,468.44 1608.98,476.69 1637.9,493.01 1661.68,516.31 1678.66,545.06 1687.65,577.3 1687.98,610.86 1679.59,643.45 1663.02,672.83 1639.33,696.99 1610.13,714.23 1577.38,723.35 1543.29,723.68 1510.2,715.16 1480.36,698.32 1455.83,674.27 1438.33,644.61 1429.07,611.35 1428.74,576.73 1437.39,543.13 1454.5,512.83 1478.93,487.94 1509.04,470.17 1542.81,460.77 1577.95,460.44 1612.06,469.23 1642.81,486.6 1668.08,511.4 1686.12,541.97 1695.65,576.25 1695.98,611.92 1687.05,646.54 1669.42,677.75 1644.25,703.39 1613.22,721.68 1578.43,731.35 1542.24,731.68 1507.11,722.62 1475.45,704.72 1449.43,679.18 1430.87,647.7 1421.07,612.4 1420.74,575.68 1424.49,561.15 1425.28,558.09 1429.94,540.04 1448.1,507.92 1474.01,481.54 1505.95,462.71 1541.76,452.77 1579,452.44 1615.15,461.78 1647.73,480.2 1674.48,506.49 1693.57,538.88 1703.65,575.2 1703.98,612.97 1694.5,649.63 1675.82,682.66 1649.16,709.79 1616.31,729.14 1579.49,739.35 1541.19,739.68 1504.02,730.07 1470.53,711.12 1443.5,684.56
  signal2 w8: 1202.52,769.32 1217.55,751.58 v1@1217.77,751.32 ; 1202.53,398.21 1217.56,380.47 v1@1217.78,380.21 ; 1540.32,594.06 v1(1555.28,576.26) v1@1555.57,576.06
